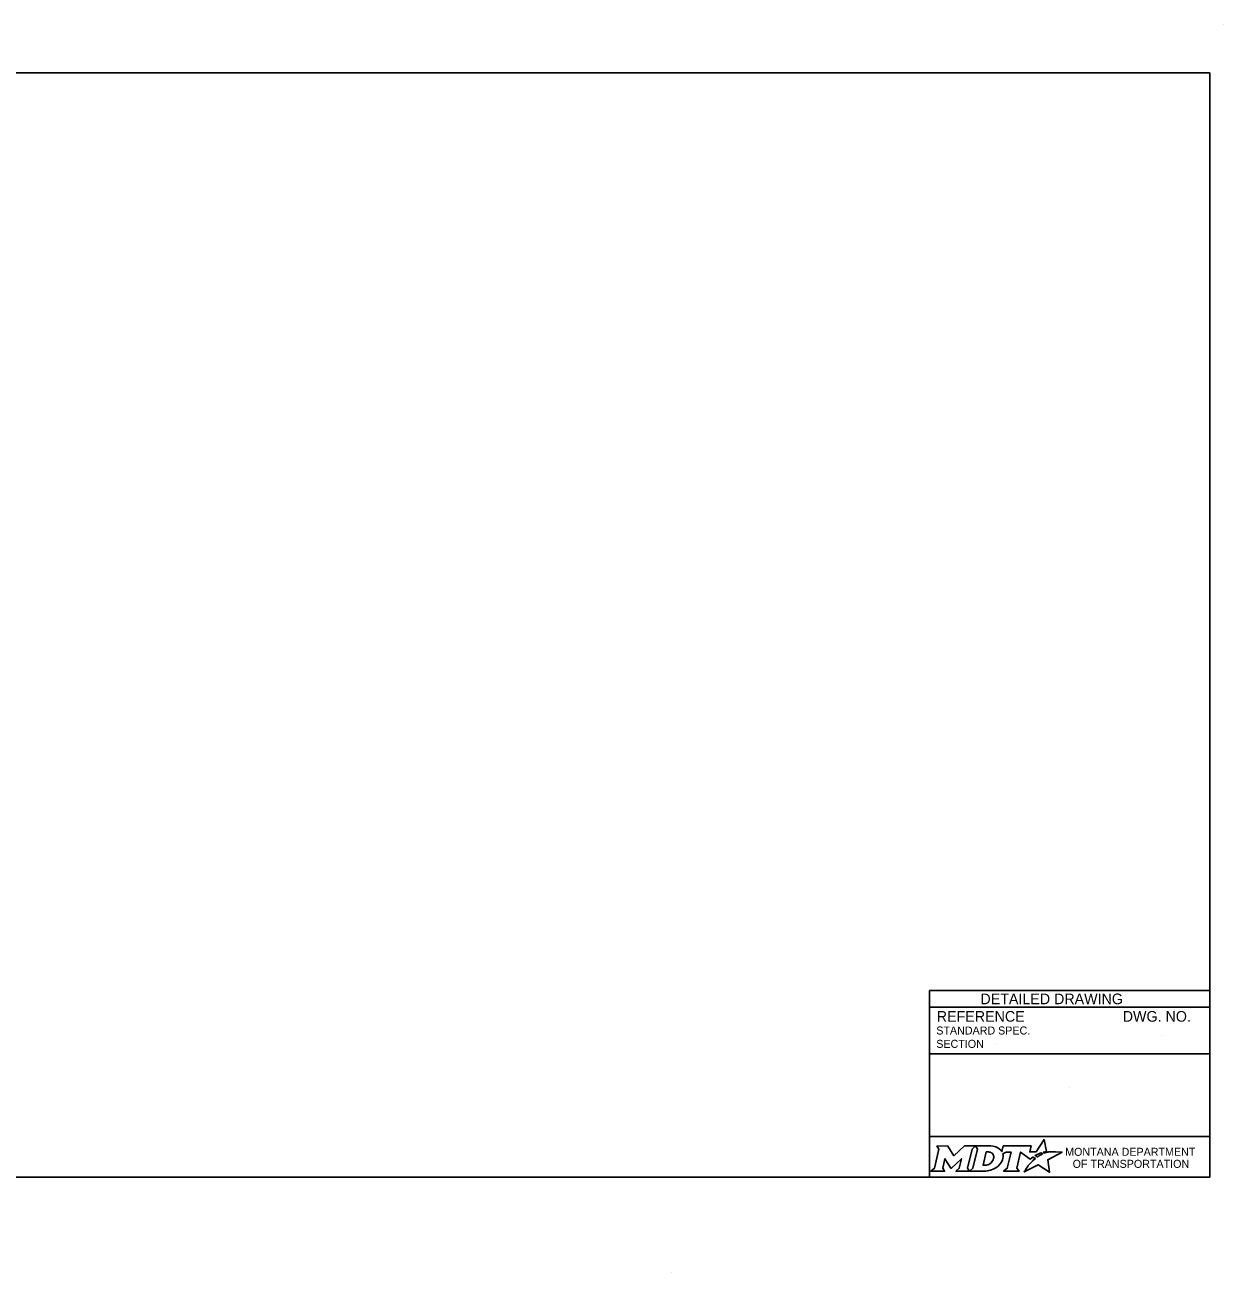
# Model space of a CAD drawing. Extents: x 49991.4 to 50028.3, y 49987.6 to 50011.4.
# Drawn here: x 50012.06 to 50021.04, y 49999.18 to 50008.52 of the extents above; entities that cross this region are included whole.
import ezdxf

# ---------------------------------------------------------------- set-up
doc = ezdxf.new("R2010")
doc.units = 0
for name, color, linetype in [('Default', 7, 'Continuous'), ('Level 1', 7, 'Continuous'), ('Level 4', 7, 'Continuous')]:
    doc.layers.add(name, color=color, linetype=linetype)

msp = doc.modelspace()

# ---------------------------------------------------------------- linework, layer by layer
at = {"layer": 'Default'}
for points in [[(50018.8933, 50000.1206), (50018.9074, 50000.0972), (50018.8739, 49999.9539), (50018.8482, 49999.9314), (50018.9498, 49999.9314), (50018.9363, 49999.9542), (50018.9525, 50000.0243), (50018.9962, 49999.9553), (50019.0015, 49999.9553), (50019.0766, 50000.0248), (50019.0602, 49999.9537), (50019.0355, 49999.9317), (50019.1371, 49999.9317), (50019.1233, 49999.955), (50019.1565, 50000.0974)], [(50019.1565, 50000.0974), (50019.1818, 50000.1206), (50019.0994, 50000.1206), (50019.0198, 50000.0476), (50018.9753, 50000.1203), (50018.8933, 50000.1206)], [(50019.2954, 50000.1206), (50019.1818, 50000.1206), (50019.1965, 50000.0977), (50019.1626, 49999.9539), (50019.1371, 49999.9317), (50019.2477, 49999.9317)], [(50019.7003, 50000.0679), (50019.69, 50000.0735), (50019.7016, 50000.0763), (50019.7132, 50000.0783), (50019.6958, 50000.1684), (50019.6363, 50000.0771), (50019.589, 50000.0764), (50019.5993, 50000.1205), (50019.3901, 50000.1206), (50019.38, 50000.0781), (50019.3742, 50000.0864)], [(50019.3194, 50000.0339), (50019.3182, 50000.0258), (50019.315, 50000.0165), (50019.3108, 50000.0083), (50019.3052, 50000.0008), (50019.2987, 49999.9939), (50019.2908, 49999.9876), (50019.2825, 49999.9829), (50019.2734, 49999.979), (50019.2643, 49999.9767), (50019.2551, 49999.9758), (50019.2392, 49999.9758), (50019.2628, 50000.0758), (50019.2788, 50000.0758), (50019.2864, 50000.0752), (50019.294, 50000.0733), (50019.3006, 50000.0703), (50019.3067, 50000.0661), (50019.3115, 50000.0611), (50019.3152, 50000.0551), (50019.3179, 50000.0489), (50019.3195, 50000.0415), (50019.3195, 50000.0385), (50019.3194, 50000.0339)], [(50019.3868, 50000.0615), (50019.4114, 50000.0746), (50019.4483, 50000.0746), (50019.4197, 49999.9541), (50019.3922, 49999.9314), (50019.5084, 49999.9314), (50019.4914, 49999.9543), (50019.5196, 50000.0745), (50019.5909, 50000.0228), (50019.612, 50000.0379), (50019.6317, 50000.027)], [(50019.5759, 49999.9711), (50019.5606, 49999.9467), (50019.5559, 49999.9392), (50019.5501, 49999.9306), (50019.5478, 49999.9263), (50019.6531, 49999.9794), (50019.737, 49999.9243), (50019.7239, 50000.017), (50019.8308, 50000.0754), (50019.7815, 50000.0762), (50019.7514, 50000.0766), (50019.7306, 50000.0769), (50019.7238, 50000.0754), (50019.7189, 50000.0742), (50019.7105, 50000.0719), (50019.7003, 50000.0679)], [(50019.6499, 50000.0403), (50019.6475, 50000.0386), (50019.6292, 50000.0482), (50019.6395, 50000.0539), (50019.6436, 50000.0561), (50019.6522, 50000.0601), (50019.6579, 50000.0627), (50019.6658, 50000.0657), (50019.6731, 50000.0684), (50019.6849, 50000.061), (50019.6809, 50000.0589), (50019.6763, 50000.0564), (50019.6721, 50000.0542), (50019.6671, 50000.0513), (50019.6652, 50000.0502), (50019.6625, 50000.0486), (50019.66, 50000.0472), (50019.6577, 50000.0456), (50019.6551, 50000.0438), (50019.6524, 50000.042), (50019.6499, 50000.0403)], [(50019.2934, 49999.939), (50019.3018, 49999.9416), (50019.3148, 49999.947), (50019.3352, 49999.958)], [(50019.5898, 49999.9872), (50019.5898, 49999.9872)]]:
    msp.add_lwpolyline(points, dxfattribs=at)
for centre, radius, start, end in [((50019.2745, 50000.0595), 0.1183, 300.91025, 339.13831), ((50019.3185, 50000.0422), 0.0709, 339.53292, 15.85821)]:
    msp.add_arc(centre, radius, start, end, dxfattribs=at)
for centre, major_axis, ratio, start_param, end_param in [((50019.2933, 50000.0732), (0.0834, -0.0037), 0.568097, 0.61298, 1.570796), ((50019.3489, 50000.0805), (0.0361, -0.0295), 0.469099, 1.225588, 1.570796), ((50019.5996, 49999.9974), (-0.0098, -0.0102), 0.016458, 3.141593, 6.279097), ((50019.6206, 50000.0173), (-0.0112, -0.0097), 0.021651, 3.157348, 6.283185), ((50019.248, 50000.08), (0, 0.1484), 0.987302, 3.139398, 3.456847), ((50019.5829, 49999.9791), (-0.00694, -0.00806), 0.008222, 0, 3.137361)]:
    msp.add_ellipse(centre, major_axis=major_axis, ratio=ratio, start_param=start_param, end_param=end_param, dxfattribs=at)
at = {"layer": 'Level 1'}
for p, q in [((50021.0378, 50008.5236), (50021.0378, 50008.5236)), ((50016.9001, 49999.1756), (50016.9001, 49999.1756))]:
    msp.add_line(p, q, dxfattribs=at)
msp.add_lwpolyline([(50020.9378, 50008.1646), (50009.7374, 50008.1646), (50009.7374, 49999.8856), (50020.9378, 49999.8856)], close=True, dxfattribs=at)
at = {"layer": 'Level 4'}
for p, q in [((50020.9378, 50001.2856), (50018.8378, 50001.2856)), ((50018.8378, 50001.2856), (50018.8378, 49999.8856)), ((50020.9378, 50001.1606), (50018.8378, 50001.1606)), ((50020.5739, 50000.9455), (50020.5739, 50000.9455)), ((50019.3321, 50000.8861), (50019.3321, 50000.8861)), ((50020.9378, 50000.8106), (50018.8378, 50000.8106)), ((50019.8878, 50000.5615), (50019.8878, 50000.5615)), ((50020.9378, 50000.1925), (50018.8378, 50000.1925))]:
    msp.add_line(p, q, dxfattribs=at)

# ---------------------------------------------------------------- texts
at = {"layer": 'Default'}
for s, p in [('MONTANA DEPARTMENT', (50019.854, 50000.0468)), ('OF TRANSPORTATION', (50019.9102, 49999.9568))]:
    msp.add_text(s, height=0.06, dxfattribs=at).set_placement(p)
at = {"layer": 'Level 4'}
for s, height, p in [('DETAILED DRAWING', 0.0799, (50019.2188, 50001.1831)), ('REFERENCE', 0.08, (50018.8914, 50001.0522)), ('DWG. NO.', 0.08, (50020.2856, 50001.0522)), ('STANDARD SPEC.', 0.06, (50018.8881, 50000.9562)), ('SECTION', 0.06, (50018.8881, 50000.8562))]:
    msp.add_text(s, height=height, dxfattribs=at).set_placement(p)

doc.saveas('drawing.dxf')
